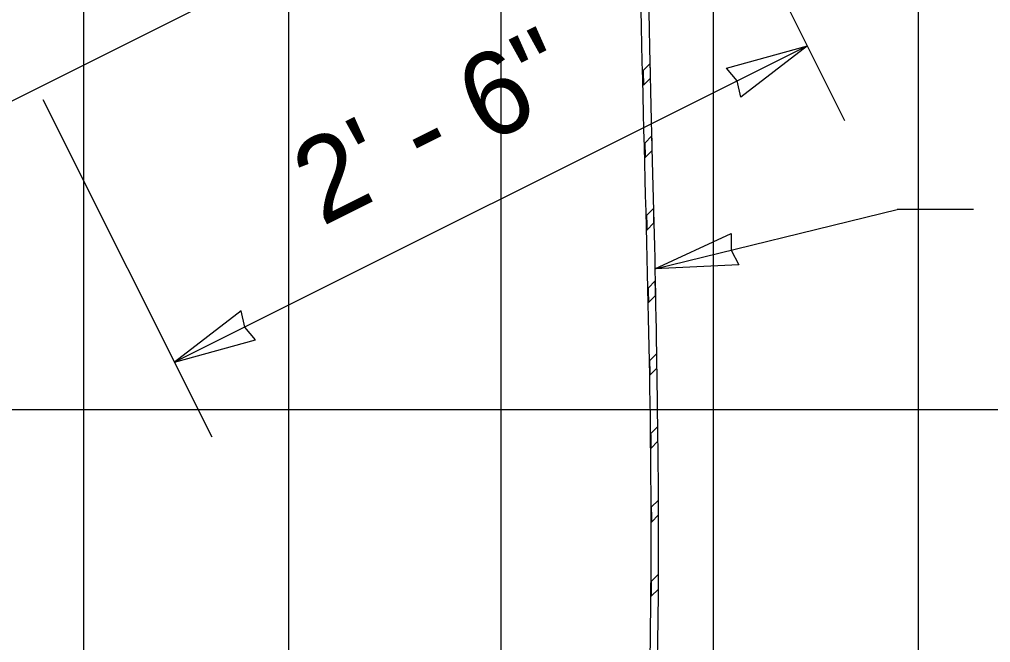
# Model space of a CAD drawing. Extents: x 99862 to 104211, y 98939 to 105076.
# Drawn here: x 102084.3 to 102269.6, y 101668.3 to 101787.2 of the extents above; entities that cross this region are included whole.
import ezdxf

# ---------------------------------------------------------------- set-up
doc = ezdxf.new("R2010")
doc.units = 0
for name, color, linetype in [('Level 10', 7, 'Continuous'), ('Level 15', 7, 'Continuous'), ('Level 18', 7, 'Continuous'), ('Level 20', 7, 'Continuous'), ('Level 5', 7, 'Continuous'), ('Level 7', 7, 'Continuous')]:
    doc.layers.add(name, color=color, linetype=linetype)

msp = doc.modelspace()

# ---------------------------------------------------------------- linework, layer by layer
at = {"layer": 'Level 10'}
for p, q in [((102135.7, 101659.02), (102135.7, 101983.85)), ((102216.7, 101659.02), (102216.7, 101983.85)), ((102096.55, 101945.6), (102096.55, 101659.02)), ((102255.85, 101659.02), (102255.85, 101945.6)), ((101917.45, 101689.01), (102208.48, 101834.53)), ((102434.95, 101712.74), (101964.89, 101712.74))]:
    msp.add_line(p, q, dxfattribs=at)
at = {"layer": 'Level 15'}
for p, q in [((102176.2, 101659.31), (102176.2, 102033.63)), ((102241.8, 101767.9), (102210.44, 101830.61)), ((102234.64, 101782.21), (102113.9, 101721.83)), ((102121.05, 101707.52), (102088.85, 101771.92)), ((102205.53, 101739.66), (102251.75, 101751)), ((102266.35, 101751), (102251.75, 101751))]:
    msp.add_line(p, q, dxfattribs=at)
msp.add_lwpolyline([(102205.53, 101739.66), (102220.06, 101746.4), (102220.09, 101743.23), (102221.53, 101740.41)], close=True, dxfattribs=at)
at = {"layer": 'Level 18'}
for p, q in [((102204.65, 101778.82), (102203.3, 101777.47)), ((102203.36, 101774.7), (102204.71, 101776.05)), ((102204.97, 101765), (102203.62, 101763.65)), ((102203.69, 101760.88), (102205.04, 101762.24)), ((102205.3, 101751.18), (102203.95, 101749.83)), ((102204.01, 101747.06), (102205.36, 101748.42)), ((102205.61, 101737.35), (102204.25, 101735.99)), ((102204.31, 101733.22), (102205.66, 101734.58)), ((102205.88, 101723.48), (102204.52, 101722.12)), ((102204.57, 101719.34), (102205.93, 101720.7)), ((102206.1, 101709.55), (102204.73, 101708.19)), ((102204.76, 101705.39), (102206.13, 101706.76)), ((102206.23, 101695.54), (102204.85, 101694.17)), ((102204.86, 101691.35), (102206.24, 101692.73)), ((102206.24, 101681.41), (102204.85, 101680.02)), ((102204.83, 101677.17), (102206.22, 101678.56))]:
    msp.add_line(p, q, dxfattribs=at)
for points in [[(102204.65, 101778.82), (102204.65, 101778.82)], [(102203.95, 101749.83), (102203.95, 101749.83)], [(102204.25, 101735.99), (102204.25, 101735.99)], [(102204.52, 101722.12), (102204.52, 101722.12)], [(102204.73, 101708.19), (102204.73, 101708.19)], [(102204.76, 101705.39), (102204.76, 101705.39)], [(102204.85, 101694.17), (102204.85, 101694.17)], [(102204.86, 101691.35), (102204.86, 101691.35)], [(102204.85, 101680.02), (102204.85, 101680.02)], [(102204.83, 101677.17), (102204.83, 101677.17)]]:
    msp.add_lwpolyline(points, dxfattribs=at)
for points in [[(102204.71, 101776.05), (102204.69, 101776.97), (102204.67, 101777.9), (102204.65, 101778.82)], [(102203.3, 101777.47), (102203.32, 101776.54), (102203.34, 101775.62), (102203.36, 101774.7)], [(102205.04, 101762.24), (102205.02, 101763.16), (102205, 101764.08), (102204.97, 101765)], [(102203.62, 101763.65), (102203.64, 101762.73), (102203.67, 101761.8), (102203.69, 101760.88)], [(102203.95, 101749.83), (102203.97, 101748.91), (102203.99, 101747.98), (102204.01, 101747.06)], [(102205.36, 101748.42), (102205.34, 101749.34), (102205.32, 101750.26), (102205.3, 101751.18)], [(102205.66, 101734.58), (102205.64, 101735.5), (102205.62, 101736.42), (102205.61, 101737.35)], [(102204.25, 101735.99), (102204.27, 101735.07), (102204.29, 101734.14), (102204.31, 101733.22)], [(102204.52, 101722.12), (102204.54, 101721.19), (102204.55, 101720.26), (102204.57, 101719.34)], [(102205.93, 101720.7), (102205.91, 101721.62), (102205.9, 101722.55), (102205.88, 101723.48)], [(102206.13, 101706.76), (102206.12, 101707.69), (102206.11, 101708.62), (102206.1, 101709.55)], [(102204.73, 101708.19), (102204.74, 101707.25), (102204.75, 101706.32), (102204.76, 101705.39)], [(102206.24, 101692.73), (102206.24, 101693.66), (102206.23, 101694.6), (102206.23, 101695.54)], [(102204.85, 101694.17), (102204.86, 101693.22), (102204.86, 101692.29), (102204.86, 101691.35)], [(102206.22, 101678.56), (102206.23, 101679.51), (102206.23, 101680.46), (102206.24, 101681.41)], [(102204.85, 101680.02), (102204.84, 101679.06), (102204.83, 101678.11), (102204.83, 101677.17)]]:
    msp.add_open_spline(points, degree=2, dxfattribs=at)
at = {"layer": 'Level 5'}
for points in [[(102205.89, 101659.02), (102205.96, 101661.65), (102206.02, 101664.33), (102206.13, 101670.3), (102206.18, 101673.61), (102206.24, 101680.4), (102206.25, 101683.88), (102206.25, 101694.53), (102206.2, 101701.94), (102205.7, 101740.11), (102204.65, 101774.3), (102203.45, 101840.6), (102203.3, 101872.73), (102203.25, 101908.6), (102203.25, 101915.56), (102203.25, 101928.97), (102203.25, 101935.41), (102203.25, 101954.01), (102203.25, 101976.97), (102203.25, 102000.45), (102203.25, 102013.32), (102203.25, 102018.46), (102203.25, 102021.03), (102203.25, 102028.79), (102203.24, 102034.03), (102203.15, 102046.33), (102203.06, 102053.53), (102202.87, 102065.32)], [(102204.51, 101659.02), (102204.68, 101665.82), (102205.4, 101707.76), (102201.87, 101809.25), (102201.87, 101936.43), (102201.87, 102002.78), (102201.87, 102042.14), (102201.6, 102063.76)]]:
    msp.add_open_spline(points, degree=3, dxfattribs=at)
at = {"layer": 'Level 7'}
for points in [[(102234.64, 101782.21), (102221.96, 101772.42), (102221.23, 101775.5), (102219.2, 101777.93)], [(102113.9, 101721.83), (102129.34, 101726.11), (102127.31, 101728.54), (102126.58, 101731.62)]]:
    msp.add_lwpolyline(points, close=True, dxfattribs=at)

# ---------------------------------------------------------------- texts
at = {"layer": 'Level 20'}
msp.add_text('2\' - 6"', height=16, rotation=26.565, dxfattribs=at).set_placement((102142.02, 101747.68))

doc.saveas('drawing.dxf')
